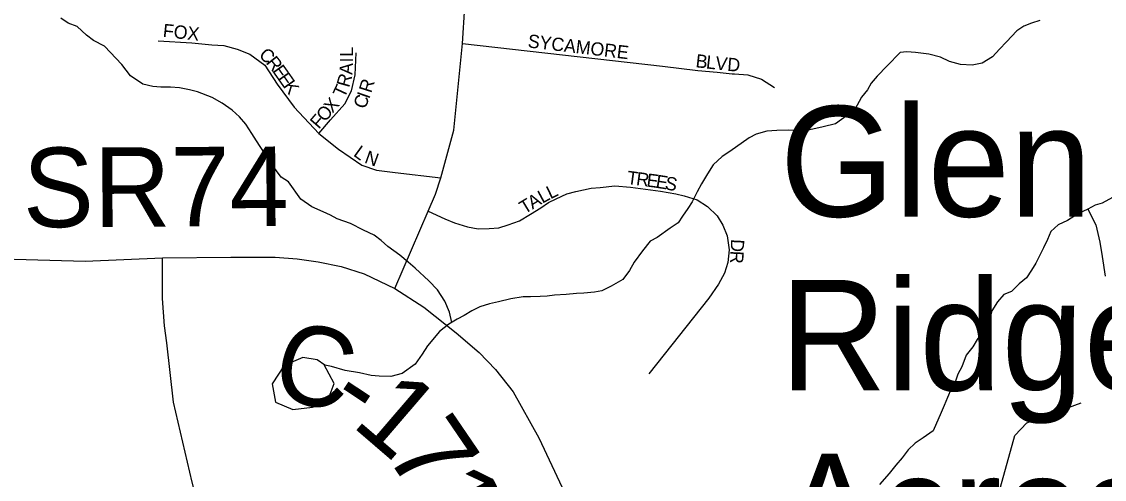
# Model space of a CAD drawing. Extents: x 1310247 to 1664935, y 235267 to 584339.
# Drawn here: x 1464596 to 1468683, y 406962 to 408689 of the extents above; entities that cross this region are included whole.
import ezdxf

# ---------------------------------------------------------------- set-up
doc = ezdxf.new("R2010")
doc.units = 0
for name, color, linetype in [('GM_X_County_Road', 7, 'Continuous'), ('GM_X_County_Road_Text', 7, 'Continuous'), ('GM_X_Minor_Lake', 7, 'Continuous'), ('GM_X_Minor_River', 7, 'Continuous'), ('GM_X_Township_Road', 7, 'Continuous'), ('GM_X_Township_Subdivision', 7, 'Continuous'), ('GM_X_Township_Subdivision_Text', 7, 'Continuous'), ('GM_X_Unincorporated_Text', 7, 'Continuous')]:
    doc.layers.add(name, color=color, linetype=linetype)

msp = doc.modelspace()

# ---------------------------------------------------------------- linework, layer by layer
at = {"layer": 'GM_X_County_Road'}
for points in [[(1463765.5, 407815.2), (1464835.2, 407785.6), (1465128.1, 407797.3), (1465385.2, 407800.2), (1465552.6, 407800.2), (1465635.7, 407794.4), (1465715.7, 407782.8), (1465801.6, 407765.3), (1465889, 407737.6), (1466004.1, 407682.3), (1466114.7, 407612.4), (1466235.6, 407514.8), (1466323, 407440.6), (1466384.1, 407376.5), (1466451.1, 407292), (1466548.7, 407118.7), (1466636.3, 406932)], [(1464261.6, 404341), (1464360.9, 404424.5), (1464481.9, 404528.9), (1464612.1, 404636.6), (1464642.1, 404661.6), (1464793.7, 404810), (1464968.7, 405007.5), (1465024.6, 405068.3), (1465139.1, 405255.4), (1465251.2, 405451.3), (1465306.3, 405572.3), (1465346, 405729.9), (1465397.7, 405894.8), (1465397.7, 405972.4), (1465399.2, 406148.8), (1465365.4, 406405.6), (1465304, 406699.8), (1465239.3, 406951.9), (1465169.5, 407252.9), (1465143.8, 407477.1), (1465134.7, 407541.8), (1465128.1, 407645.1), (1465128.1, 407797.3)]]:
    msp.add_lwpolyline(points, dxfattribs=at)
at = {"layer": 'GM_X_Minor_Lake'}
for points in [[(1465739.8, 407392.9), (1465711.3, 407413.1), (1465657.4, 407422.2), (1465586.6, 407391.5), (1465541.1, 407322.2), (1465553.7, 407253.7), (1465619.4, 407226.3), (1465693.7, 407234.8), (1465754.3, 407255.7)], [(1465754.3, 407255.7), (1465760.9, 407283.7), (1465775.7, 407323.5), (1465737.9, 407394.3)]]:
    msp.add_lwpolyline(points, dxfattribs=at)
at = {"layer": 'GM_X_Minor_River'}
for points in [[(1466219.9, 407554.5), (1466210.9, 407593.5), (1466193.5, 407634), (1466166.1, 407676.6), (1466132.6, 407711.4), (1466081.2, 407758.5), (1466055.5, 407781), (1466023.8, 407807.7), (1465978.2, 407840.6), (1465952.5, 407863.2), (1465926.7, 407883.7), (1465886.9, 407902.5), (1465837.1, 407927.4), (1465787.2, 407944.4), (1465761.4, 407958.9), (1465733.5, 407971.4), (1465691.6, 407990.2), (1465650, 408019.1), (1465602.9, 408084.2), (1465575.1, 408102.7), (1465539.8, 408149.6), (1465512.4, 408192.2), (1465483.1, 408238.9), (1465465.5, 408267.3), (1465442, 408301.9), (1465418.4, 408330.4), (1465390.7, 408355), (1465353, 408381.8), (1465315.2, 408402.5), (1465259.3, 408423.6), (1465229.4, 408432.2), (1465191.3, 408438.8), (1465157.3, 408441.5), (1465121.1, 408442.1), (1465091.1, 408444.6), (1465053.1, 408453.3), (1465007.4, 408484.2), (1464974, 408527), (1464909, 408596.4), (1464867.2, 408617.2), (1464841.4, 408637.8), (1464805.8, 408670.5), (1464771.9, 408683.2), (1464744.1, 408701.8)], [(1468439.6, 408693.2), (1468407.3, 408683.7), (1468379, 408672.2), (1468352.6, 408654.5), (1468313.7, 408613.1), (1468287.2, 408585.4), (1468260.6, 408555.7), (1468222, 408532.3), (1468183.8, 408525), (1468139.7, 408527.7), (1468097.7, 408538.5), (1468063.8, 408555.2), (1468019.9, 408566), (1467969.8, 408572.9), (1467937.7, 408575.5), (1467911.6, 408571.9), (1467862.6, 408522.6), (1467825.8, 408483), (1467803.2, 408457.3), (1467788.8, 408431.5), (1467766.2, 408403.8), (1467741.4, 408358), (1467712.9, 408336.4), (1467668.2, 408303), (1467621.8, 408291.8), (1467571.4, 408280.6), (1467529.2, 408277.3), (1467489.1, 408280.1), (1467446.9, 408278.8), (1467408.7, 408275.5), (1467368.4, 408264.1), (1467342.1, 408250.5), (1467268.9, 408199.6), (1467240.5, 408180), (1467205.9, 408148.5), (1467185.2, 408114.7), (1467162.5, 408076.9), (1467145.9, 408047.1), (1467127.2, 408009.2), (1467110.7, 407983.4), (1467090.2, 407955.7), (1467073.7, 407929.8), (1467043.3, 407910.3), (1466994.5, 407875), (1466968.2, 407861.4), (1466939.4, 407823.8), (1466908.6, 407782.1), (1466890, 407750.3), (1466865.3, 407716.6), (1466820.8, 407691.3), (1466786.3, 407673.8), (1466758.1, 407668.3), (1466717.9, 407665), (1466689.8, 407663.4), (1466651.6, 407660.1), (1466607.4, 407656.9), (1466579.2, 407653.3), (1466553.1, 407651.8), (1466516.9, 407650.4), (1466488.9, 407650.9), (1466442.6, 407643.7), (1466396.2, 407632.4), (1466362, 407625), (1466325.6, 407613.6), (1466295.3, 407598.1), (1466266.9, 407580.5), (1466240.5, 407566.9), (1466208.1, 407547.4), (1466173.5, 407519.9), (1466128.4, 407466.4), (1466107.8, 407434.6), (1466081.1, 407397), (1466032.3, 407361.7), (1465990, 407350.3), (1465945.8, 407351.1), (1465915.8, 407353.7), (1465871.8, 407364.5), (1465817.7, 407373.5), (1465765.8, 407388.4), (1465739.8, 407392.9)], [(1468713.3, 408025.6), (1468674.8, 408004.2), (1468648.6, 407996.6), (1468620.2, 407981.1), (1468585.8, 407965.6), (1468543.2, 407938.2), (1468508.8, 407922.8), (1468480.3, 407897.2), (1468467.8, 407867.2), (1468453.2, 407835.4), (1468438.6, 407807.5), (1468424.1, 407777.6), (1468407.6, 407751.8), (1468389, 407722), (1468360.6, 407700.4), (1468332, 407670.8), (1468303.7, 407659.2), (1468279.1, 407631.6), (1468258.5, 407597.8), (1468250, 407569.8), (1468235.3, 407533.9), (1468202.4, 407490.3), (1468185.9, 407462.5), (1468161.3, 407430.8), (1468144.5, 407386.9), (1468130, 407359), (1468121.5, 407333.1), (1468104.9, 407303.2), (1468090.3, 407271.3), (1468077.8, 407241.5), (1468063.1, 407205.6), (1468048.6, 407173.7), (1468036, 407145.8), (1467999.4, 407118.3), (1467969, 407098.8), (1467942.5, 407073.1), (1467919.9, 407043.4), (1467895.3, 407015.7), (1467870.7, 406984), (1467833.9, 406942.5)], [(1468620.2, 407981.1), (1468651.1, 407922), (1468665.8, 407857.5), (1468674.8, 407803.1), (1468685.3, 407728.7)]]:
    msp.add_lwpolyline(points, dxfattribs=at)
at = {"layer": 'GM_X_Township_Road'}
msp.add_lwpolyline([(1466004.1, 407682.3), (1466130, 407973.5), (1466157.7, 408038.3), (1466178.1, 408100.2), (1466227.1, 408279.2), (1466260.2, 408605.9), (1466269, 408745), (1466295.5, 408928.3), (1466315.4, 409109.3), (1466348.5, 409365.3), (1466386.2, 409741), (1466401.6, 409869.6), (1466440.9, 410163), (1466498.4, 410652.1), (1466513.8, 410796), (1466548.3, 411053), (1466559.8, 411154.7), (1466590.5, 411473.1), (1466651.9, 411877.8), (1466692.1, 412205.8), (1466719, 412411), (1466733.8, 412590.7), (1466739.2, 412674.1)], dxfattribs=at)
at = {"layer": 'GM_X_Township_Subdivision'}
for points in [[(1465111.1, 408615.9), (1465238.3, 408609), (1465313.6, 408601.8), (1465359.6, 408599.3), (1465409.2, 408585.2), (1465457.3, 408565.6), (1465514.4, 408524.6), (1465560.7, 408453.4), (1465624.8, 408366), (1465717.4, 408266.5), (1465791.4, 408207.7), (1465879.6, 408146.9), (1465934.9, 408129.1), (1466006.1, 408120.2), (1466178.1, 408100.2)], [(1466260.2, 408605.9), (1467014.4, 408521.1), (1467147.7, 408504.8), (1467221.5, 408498.1), (1467278.4, 408492.3)], [(1465717.4, 408266.5), (1465762.4, 408319), (1465815.4, 408378.6), (1465840.8, 408428.3), (1465855.1, 408487.8), (1465858.5, 408570.6)], [(1467278.4, 408492.3), (1467286.7, 408491.4), (1467337.6, 408487.6), (1467388.4, 408472.2), (1467437.3, 408440.6)], [(1466130, 407973.5), (1466193.4, 407944.4), (1466229.8, 407929.8), (1466278.5, 407914.5), (1466319.3, 407907.3), (1466360.8, 407908.7), (1466397.2, 407910.9), (1466432.9, 407922.6), (1466475.1, 407937.1), (1466516.6, 407962.6), (1466556, 407986.6), (1466585.1, 408006.3), (1466613.5, 408020.9), (1466653.5, 408039), (1466687.7, 408048.5), (1466745.3, 408060.9), (1466780.2, 408063.8), (1466835, 408069.1), (1466893.7, 408064.9), (1467007.4, 408049.2), (1467064.9, 408039), (1467096.9, 408031.8), (1467145.7, 408016.5), (1467184.4, 407991.5), (1467221.4, 407956), (1467242.4, 407921.4), (1467259.3, 407880.3), (1467266.6, 407828.6), (1467261.5, 407780.6), (1467248.4, 407739.8), (1467226.5, 407698.3), (1467189.4, 407645.9), (1466963, 407360.2)], [(1467824.8, 406114.4), (1467868.2, 406216.5), (1467920.5, 406303.8), (1467967.3, 406383.6), (1468015.4, 406453.8), (1468063.6, 406525.3), (1468115.9, 406594.8), (1468176.4, 406670.5), (1468221.1, 406748.2), (1468272.4, 406864.4), (1468344.3, 407127.8), (1468390, 407175.1), (1468595.4, 407250.6)]]:
    msp.add_lwpolyline(points, dxfattribs=at)

# ---------------------------------------------------------------- texts
at = {"layer": 'GM_X_County_Road_Text'}
for s, rotation, p in [('SR74', 0.2957, (1464601.4, 407913)), ('C', 345.2036, (1465526.8, 407282.3)), ('-', 326.5373, (1465741.5, 407229.9)), ('1', 319.3169, (1465836.3, 407168)), ('7', 304.3107, (1465962.7, 407063)), ('1', 297.1725, (1466061.8, 406918.9))]:
    msp.add_text(s, height=300, rotation=rotation, dxfattribs=at).set_placement(p)
at = {"layer": 'GM_X_Township_Subdivision_Text'}
for s, rotation, p in [('FOX', 353.8878, (1465127.3, 408631.5)), ('SYCAMORE', 353.2473, (1466504.6, 408591.9)), ('L', 90, (1465847.2, 408556.9)), ('C', 316.872, (1465488.3, 408559.3)), ('R', 308.5119, (1465515.9, 408533.7)), ('I', 90.0309, (1465847.3, 408534.9)), ('B', 353.5016, (1467138.2, 408517.1)), ('L', 353.5242, (1467177.6, 408512.6)), ('V', 353.5174, (1467212.5, 408508.7)), ('D', 355.4512, (1467258.1, 408503.5)), ('E', 305.236, (1465540.1, 408503.3)), ('A', 86.5023, (1465844.5, 408487.6)), ('E', 305.1979, (1465560.4, 408474.5)), ('K', 305.1997, (1465580.7, 408445.8)), ('R', 74.2036, (1465831.7, 408438)), ('R', 72.394, (1465915.3, 408417.2)), ('T', 64.9734, (1465813.8, 408397.9)), ('I', 70.8449, (1465907.6, 408395)), ('X', 49.3157, (1465769.5, 408341.2)), ('C', 68.83, (1465892.6, 408356.3)), ('F', 49.292, (1465717.8, 408281.1)), ('O', 49.3083, (1465740.8, 408307.8)), ('L', 324.2177, (1465845.2, 408184.9)), ('N', 340.3108, (1465887.1, 408157.4)), ('T', 352.3837, (1466878.7, 408077.1)), ('R', 352.3508, (1466913.6, 408072.5)), ('E', 352.3861, (1466952.8, 408067.2)), ('E', 350.9734, (1466987.4, 408062.6)), ('S', 349.0866, (1467021.7, 408057.1)), ('L', 25.9542, (1466591.9, 408018.3)), ('T', 31.3104, (1466494.1, 407961.4)), ('A', 30.634, (1466524, 407979.6)), ('L', 28.4469, (1466561.4, 408001.8)), ('D', 267.2009, (1467274, 407869.3)), ('R', 267.2522, (1467271.9, 407825.3))]:
    msp.add_text(s, height=50, rotation=rotation, dxfattribs=at).set_placement(p)
at = {"layer": 'GM_X_Unincorporated_Text'}
for s, p in [('Glen', (1467458.2, 407953.2)), ('Ridge', (1467458.2, 407297.6)), ('Acres', (1467458.2, 406642))]:
    msp.add_text(s, height=417, rotation=0, dxfattribs=at).set_placement(p)

doc.saveas('drawing.dxf')
